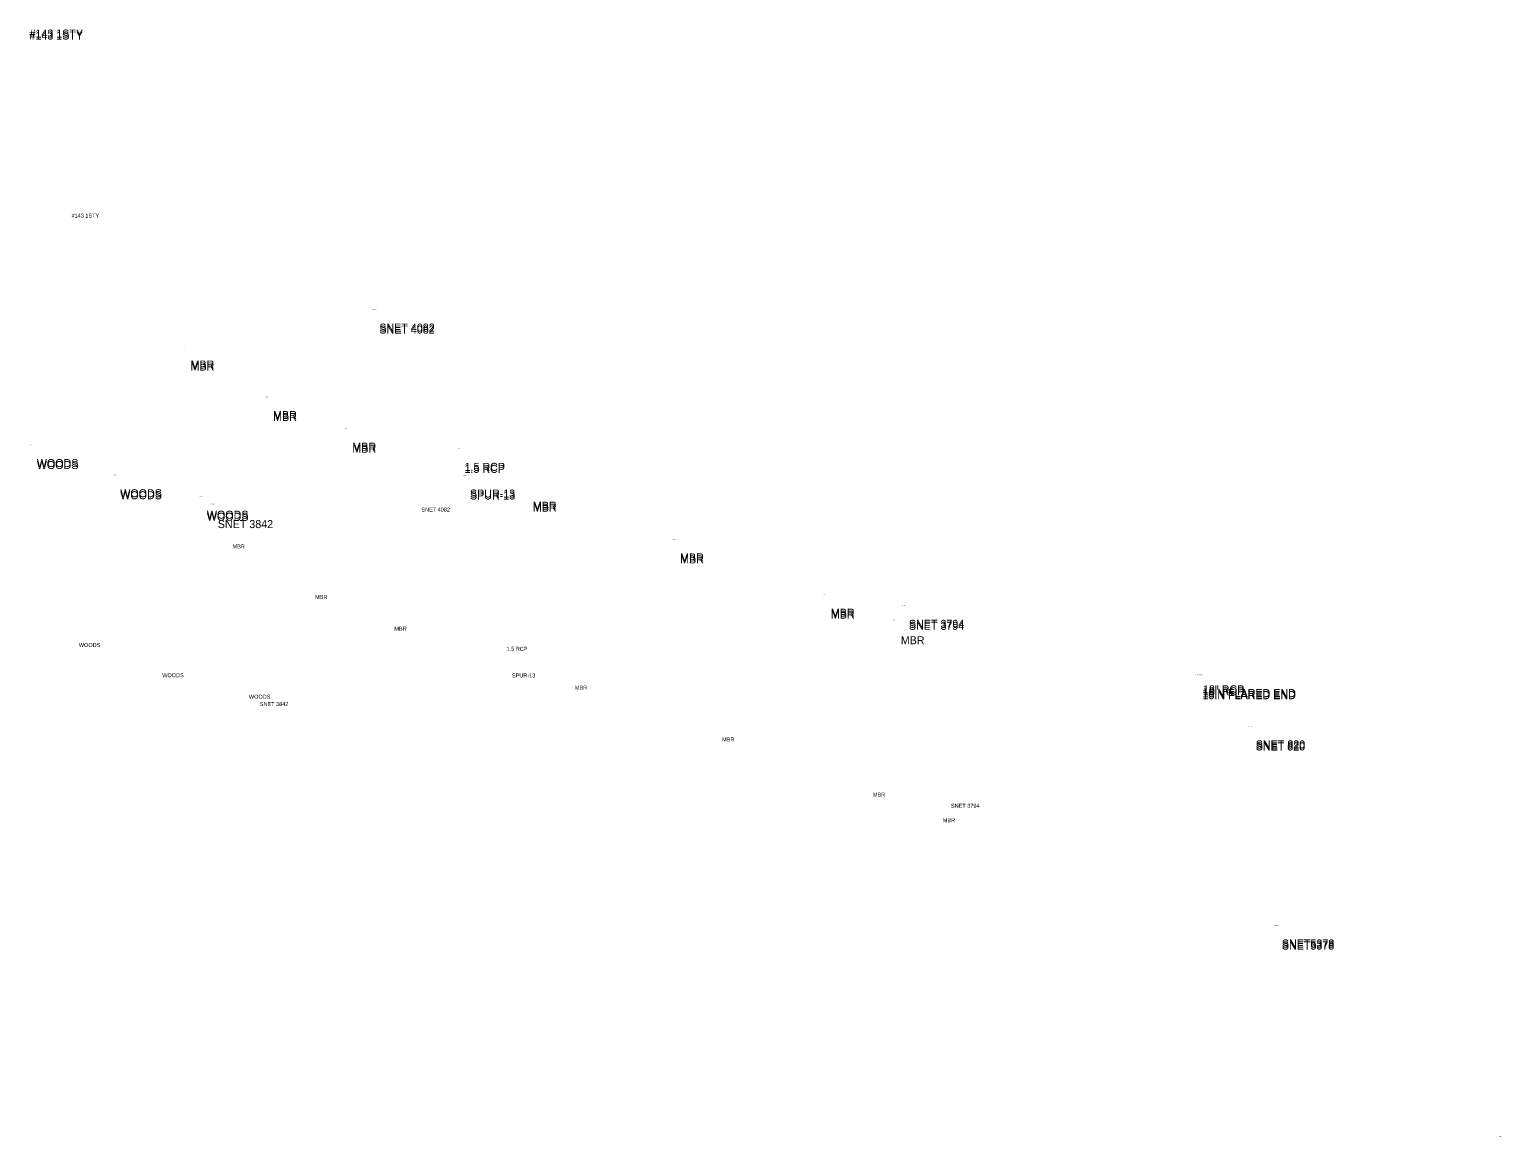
# Model space of a CAD drawing. Extents: x 5447 to 709667, y 4528 to 375472.
# Drawn here: x 706654 to 707243, y 374513 to 374956 of the extents above; entities that cross this region are included whole.
import ezdxf

# ---------------------------------------------------------------- set-up
doc = ezdxf.new("R2010")
doc.units = 0
doc.layers.add('SV_SURVEY_NOTES', color=7, linetype='Continuous')

msp = doc.modelspace()

# ---------------------------------------------------------------- texts
at = {"layer": 'SV_SURVEY_NOTES'}
for s, height, p in [('#143 1STY', 3.2, (706654.29, 374952.39)), ('#143 1STY', 3.2, (706654.29, 374952.39)), ('#143 1STY', 3.2, (706654.29, 374952.39)), ('#143 1STY', 3.2, (706654.29, 374952.39)), ('#143 1STY', 3.2, (706654.29, 374952.39)), ('#143 1STY', 3.2, (706654.29, 374952.39)), ('#143 1STY', 3.2, (706654.29, 374952.39)), ('#143 1STY', 3.2, (706654.29, 374952.39)), ('#143 1STY', 3.2, (706654.29, 374951.59)), ('#143 1STY', 3.2, (706654.29, 374951.59)), ('#143 1STY', 3.2, (706654.29, 374951.59)), ('#143 1STY', 1.6, (706671.09, 374880.39)), ('SNET 4082', 0.25, (706791.22, 374843.48)), ('SNET 4082', 3.2, (706794.17, 374834.76)), ('SNET 4082', 3.2, (706794.17, 374834.76)), ('SNET 4082', 3.2, (706794.17, 374834.76)), ('SNET 4082', 3.2, (706794.17, 374834.76)), ('SNET 4082', 3.2, (706794.17, 374834.76)), ('SNET 4082', 3.2, (706794.17, 374834.76)), ('SNET 4082', 3.2, (706794.17, 374834.76)), ('SNET 4082', 3.2, (706794.17, 374834.76)), ('SNET 4082', 3.2, (706794.17, 374833.96)), ('SNET 4082', 3.2, (706794.17, 374833.96)), ('SNET 4082', 3.2, (706794.17, 374833.96)), ('MBR', 0.25, (706715.73, 374828.71)), ('MBR', 3.2, (706718.68, 374819.98)), ('MBR', 3.2, (706718.68, 374819.98)), ('MBR', 3.2, (706718.68, 374819.98)), ('MBR', 3.2, (706718.68, 374819.98)), ('MBR', 3.2, (706718.68, 374819.98)), ('MBR', 3.2, (706718.68, 374819.98)), ('MBR', 3.2, (706718.68, 374819.98)), ('MBR', 3.2, (706718.68, 374819.98)), ('MBR', 3.2, (706718.68, 374819.18)), ('MBR', 3.2, (706718.68, 374819.18)), ('MBR', 3.2, (706718.68, 374819.18)), ('MBR', 0.25, (706748.74, 374808.51)), ('MBR', 3.2, (706751.69, 374799.78)), ('MBR', 3.2, (706751.69, 374799.78)), ('MBR', 3.2, (706751.69, 374799.78)), ('MBR', 3.2, (706751.69, 374799.78)), ('MBR', 3.2, (706751.69, 374799.78)), ('MBR', 3.2, (706751.69, 374799.78)), ('MBR', 3.2, (706751.69, 374799.78)), ('MBR', 3.2, (706751.69, 374799.78)), ('MBR', 3.2, (706751.69, 374798.98)), ('MBR', 3.2, (706751.69, 374798.98)), ('MBR', 3.2, (706751.69, 374798.98)), ('MBR', 0.25, (706780.43, 374795.83)), ('WOODS', 0.25, (706654.27, 374789.28)), ('MBR', 3.2, (706783.38, 374787.1)), ('MBR', 3.2, (706783.38, 374787.1)), ('MBR', 3.2, (706783.38, 374787.1)), ('MBR', 3.2, (706783.38, 374787.1)), ('MBR', 3.2, (706783.38, 374787.1)), ('MBR', 3.2, (706783.38, 374787.1)), ('MBR', 3.2, (706783.38, 374787.1)), ('MBR', 3.2, (706783.38, 374787.1)), ('MBR', 3.2, (706783.38, 374786.3)), ('MBR', 3.2, (706783.38, 374786.3)), ('MBR', 3.2, (706783.38, 374786.3)), ('1.5 RCP', 0.25, (706825.28, 374787.76)), ('WOODS', 3.2, (706657.22, 374780.56)), ('WOODS', 3.2, (706657.22, 374780.56)), ('WOODS', 3.2, (706657.22, 374780.56)), ('WOODS', 3.2, (706657.22, 374780.56)), ('WOODS', 3.2, (706657.22, 374780.56)), ('WOODS', 3.2, (706657.22, 374780.56)), ('WOODS', 3.2, (706657.22, 374780.56)), ('WOODS', 3.2, (706657.22, 374780.56)), ('WOODS', 3.2, (706657.22, 374779.76)), ('WOODS', 3.2, (706657.22, 374779.76)), ('WOODS', 3.2, (706657.22, 374779.76)), ('1.5 RCP', 3.2, (706828.23, 374779.04)), ('1.5 RCP', 3.2, (706828.23, 374779.04)), ('1.5 RCP', 3.2, (706828.23, 374779.04)), ('1.5 RCP', 3.2, (706828.23, 374779.04)), ('1.5 RCP', 3.2, (706828.23, 374779.04)), ('1.5 RCP', 3.2, (706828.23, 374779.04)), ('1.5 RCP', 3.2, (706828.23, 374779.04)), ('1.5 RCP', 3.2, (706828.23, 374779.04)), ('WOODS', 0.25, (706687.63, 374777.22)), ('SPUR-13', 0.25, (706827.45, 374777.1)), ('1.5 RCP', 3.2, (706828.23, 374778.24)), ('1.5 RCP', 3.2, (706828.23, 374778.24)), ('1.5 RCP', 3.2, (706828.23, 374778.24)), ('WOODS', 3.2, (706690.58, 374768.49)), ('WOODS', 3.2, (706690.58, 374768.49)), ('WOODS', 3.2, (706690.58, 374768.49)), ('WOODS', 3.2, (706690.58, 374768.49)), ('WOODS', 3.2, (706690.58, 374768.49)), ('WOODS', 3.2, (706690.58, 374768.49)), ('WOODS', 3.2, (706690.58, 374768.49)), ('WOODS', 3.2, (706690.58, 374768.49)), ('WOODS', 3.2, (706690.58, 374767.69)), ('WOODS', 3.2, (706690.58, 374767.69)), ('WOODS', 3.2, (706690.58, 374767.69)), ('SPUR-13', 3.2, (706830.4, 374768.37)), ('SPUR-13', 3.2, (706830.4, 374768.37)), ('SPUR-13', 3.2, (706830.4, 374768.37)), ('SPUR-13', 3.2, (706830.4, 374768.37)), ('SPUR-13', 3.2, (706830.4, 374768.37)), ('SPUR-13', 3.2, (706830.4, 374768.37)), ('SPUR-13', 3.2, (706830.4, 374768.37)), ('SPUR-13', 3.2, (706830.4, 374768.37)), ('SPUR-13', 3.2, (706830.4, 374767.57)), ('SPUR-13', 3.2, (706830.4, 374767.57)), ('SPUR-13', 3.2, (706830.4, 374767.57)), ('MBR', 0.25, (706852.6, 374772.22)), ('WOODS', 0.25, (706722.26, 374768.61)), ('SNET 3842', 0.25, (706726.63, 374765.67)), ('SNET 4082', 1.6, (706810.98, 374762.76)), ('MBR', 3.2, (706855.55, 374763.5)), ('MBR', 3.2, (706855.55, 374763.5)), ('MBR', 3.2, (706855.55, 374763.5)), ('MBR', 3.2, (706855.55, 374763.5)), ('MBR', 3.2, (706855.55, 374763.5)), ('MBR', 3.2, (706855.55, 374763.5)), ('MBR', 3.2, (706855.55, 374763.5)), ('MBR', 3.2, (706855.55, 374763.5)), ('MBR', 3.2, (706855.55, 374762.7)), ('MBR', 3.2, (706855.55, 374762.7)), ('MBR', 3.2, (706855.55, 374762.7)), ('WOODS', 3.2, (706725.21, 374759.89)), ('WOODS', 3.2, (706725.21, 374759.89)), ('WOODS', 3.2, (706725.21, 374759.89)), ('WOODS', 3.2, (706725.21, 374759.89)), ('WOODS', 3.2, (706725.21, 374759.89)), ('WOODS', 3.2, (706725.21, 374759.89)), ('WOODS', 3.2, (706725.21, 374759.89)), ('WOODS', 3.2, (706725.21, 374759.89)), ('WOODS', 3.2, (706725.21, 374759.09)), ('WOODS', 3.2, (706725.21, 374759.09)), ('WOODS', 3.2, (706725.21, 374759.09)), ('SNET 3842', 3.2, (706729.58, 374756.94)), ('SNET 3842', 3.2, (706729.58, 374756.94)), ('SNET 3842', 3.2, (706729.58, 374756.94)), ('SNET 3842', 3.2, (706729.58, 374756.94)), ('SNET 3842', 3.2, (706729.58, 374756.94)), ('SNET 3842', 3.2, (706729.58, 374756.94)), ('SNET 3842', 3.2, (706729.58, 374756.94)), ('SNET 3842', 3.2, (706729.58, 374756.94)), ('SNET 3842', 3.2, (706729.58, 374756.14)), ('SNET 3842', 3.2, (706729.58, 374756.14)), ('SNET 3842', 3.2, (706729.58, 374756.14)), ('MBR', 1.6, (706735.48, 374747.98)), ('MBR', 0.25, (706911.47, 374751.51)), ('MBR', 3.2, (706914.42, 374742.78)), ('MBR', 3.2, (706914.42, 374742.78)), ('MBR', 3.2, (706914.42, 374742.78)), ('MBR', 3.2, (706914.42, 374742.78)), ('MBR', 3.2, (706914.42, 374742.78)), ('MBR', 3.2, (706914.42, 374742.78)), ('MBR', 3.2, (706914.42, 374742.78)), ('MBR', 3.2, (706914.42, 374742.78)), ('MBR', 3.2, (706914.42, 374741.98)), ('MBR', 3.2, (706914.42, 374741.98)), ('MBR', 3.2, (706914.42, 374741.98)), ('MBR', 1.6, (706768.49, 374727.78)), ('MBR', 0.25, (706971.74, 374729.43)), ('MBR', 3.2, (706974.69, 374720.71)), ('MBR', 3.2, (706974.69, 374720.71)), ('MBR', 3.2, (706974.69, 374720.71)), ('MBR', 3.2, (706974.69, 374720.71)), ('MBR', 3.2, (706974.69, 374720.71)), ('MBR', 3.2, (706974.69, 374720.71)), ('MBR', 3.2, (706974.69, 374720.71)), ('MBR', 3.2, (706974.69, 374720.71)), ('MBR', 3.2, (706974.69, 374719.91)), ('MBR', 3.2, (706974.69, 374719.91)), ('MBR', 3.2, (706974.69, 374719.91)), ('SNET 3794', 0.25, (707002.96, 374724.97)), ('MBR', 0.25, (706999.7, 374719.19)), ('SNET 3794', 3.2, (707005.91, 374716.24)), ('SNET 3794', 3.2, (707005.91, 374716.24)), ('SNET 3794', 3.2, (707005.91, 374716.24)), ('SNET 3794', 3.2, (707005.91, 374716.24)), ('SNET 3794', 3.2, (707005.91, 374716.24)), ('SNET 3794', 3.2, (707005.91, 374716.24)), ('SNET 3794', 3.2, (707005.91, 374716.24)), ('SNET 3794', 3.2, (707005.91, 374716.24)), ('SNET 3794', 3.2, (707005.91, 374715.44)), ('SNET 3794', 3.2, (707005.91, 374715.44)), ('SNET 3794', 3.2, (707005.91, 374715.44)), ('MBR', 1.6, (706800.17, 374715.1)), ('MBR', 3.2, (707002.65, 374710.47)), ('MBR', 3.2, (707002.65, 374710.47)), ('MBR', 3.2, (707002.65, 374710.47)), ('MBR', 3.2, (707002.65, 374710.47)), ('MBR', 3.2, (707002.65, 374710.47)), ('MBR', 3.2, (707002.65, 374710.47)), ('MBR', 3.2, (707002.65, 374710.47)), ('MBR', 3.2, (707002.65, 374710.47)), ('MBR', 3.2, (707002.65, 374709.67)), ('MBR', 3.2, (707002.65, 374709.67)), ('MBR', 3.2, (707002.65, 374709.67)), ('WOODS', 1.6, (706674.02, 374708.56)), ('1.5 RCP', 1.6, (706845.03, 374707.04)), ('WOODS', 1.6, (706707.38, 374696.49)), ('SPUR-13', 1.6, (706847.2, 374696.37)), ('15IN FLARED END', 0.25, (707120.29, 374697.21)), ('WOODS', 1.6, (706742.02, 374687.89)), ('MBR', 1.6, (706872.35, 374691.5)), ('15IN FLARED END', 3.2, (707123.25, 374688.48)), ('15IN FLARED END', 3.2, (707123.25, 374688.48)), ('15IN FLARED END', 3.2, (707123.25, 374688.48)), ('15IN FLARED END', 3.2, (707123.25, 374687.68)), ('15IN FLARED END', 3.2, (707123.29, 374688.55)), ('15IN FLARED END', 3.2, (707123.29, 374688.55)), ('15IN FLARED END', 3.2, (707123.29, 374688.55)), ('15IN FLARED END', 3.2, (707123.29, 374688.55)), ('15IN FLARED END', 3.2, (707123.29, 374688.55)), ('15IN FLARED END', 3.2, (707123.29, 374687.75)), ('18" RCP', 3.2, (707123.48, 374690.04)), ('18" RCP', 3.2, (707123.48, 374690.04)), ('18" RCP', 3.2, (707123.48, 374690.04)), ('18" RCP', 3.2, (707123.48, 374690.04)), ('18" RCP', 3.2, (707123.48, 374690.04)), ('18" RCP', 3.2, (707123.48, 374689.24)), ('SNET 3842', 1.6, (706746.37, 374684.94)), ('SNET 820', 0.25, (707141.61, 374676.69)), ('MBR', 1.6, (706931.22, 374670.78)), ('SNET 820', 3.2, (707144.57, 374667.96)), ('SNET 820', 3.2, (707144.57, 374667.96)), ('SNET 820', 3.2, (707144.57, 374667.96)), ('SNET 820', 3.2, (707144.57, 374667.16)), ('SNET 820', 3.2, (707144.61, 374668.03)), ('SNET 820', 3.2, (707144.61, 374668.03)), ('SNET 820', 3.2, (707144.61, 374668.03)), ('SNET 820', 3.2, (707144.61, 374668.03)), ('SNET 820', 3.2, (707144.61, 374668.03)), ('SNET 820', 3.2, (707144.61, 374667.23)), ('MBR', 1.6, (706991.49, 374648.71)), ('SNET 3794', 1.6, (707022.71, 374644.24)), ('MBR', 1.6, (707019.45, 374638.47)), ('SNET5378', 0.25, (707152.04, 374597.04)), ('SNET5378', 3.2, (707155, 374588.31)), ('SNET5378', 3.2, (707155, 374588.31)), ('SNET5378', 3.2, (707155, 374588.31)), ('SNET5378', 3.2, (707155, 374587.51)), ('SNET5378', 3.2, (707155.03, 374588.38)), ('SNET5378', 3.2, (707155.03, 374588.38)), ('SNET5378', 3.2, (707155.03, 374588.38)), ('SNET5378', 3.2, (707155.03, 374588.38)), ('SNET5378', 3.2, (707155.03, 374588.38)), ('SNET5378', 3.2, (707155.03, 374587.58)), ('SPUR-9', 0.25, (707241.64, 374512.71)), ('SPUR-9', 0.25, (707241.64, 374512.71))]:
    msp.add_text(s, height=height, dxfattribs=at).set_placement(p)

doc.saveas('drawing.dxf')
